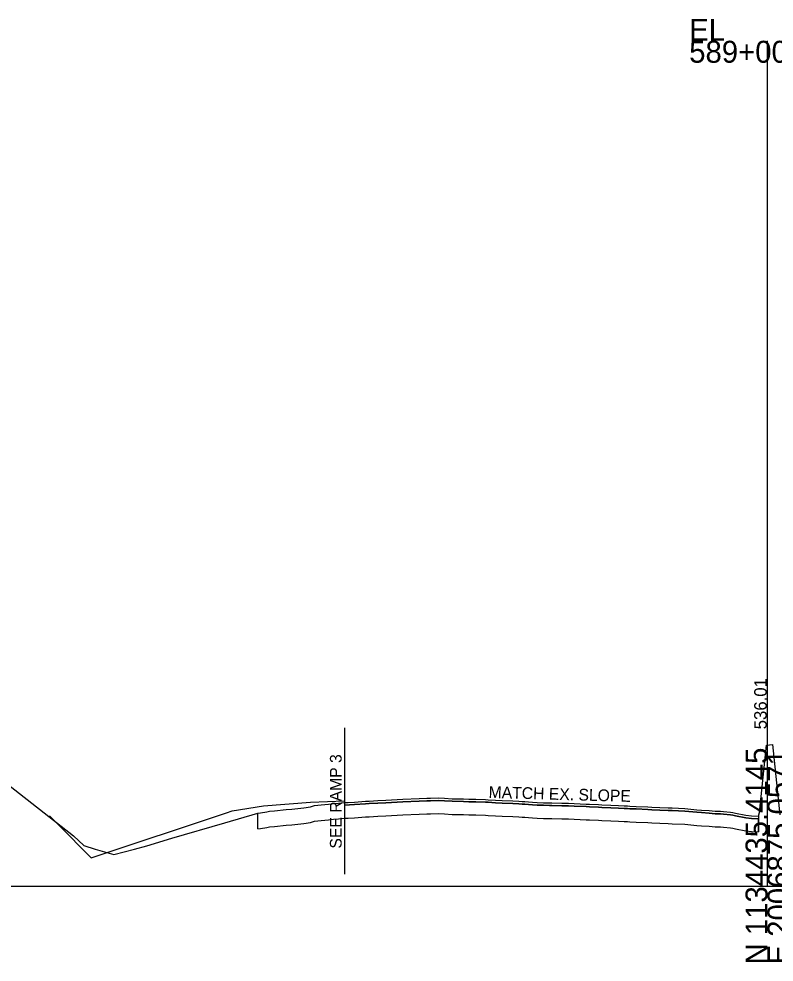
# Model space of a CAD drawing. Extents: x -201 to 2007062, y -213 to 1139737.
# Drawn here: x 1154.4 to 1250.8, y 3490.3 to 3610.7 of the extents above; entities that cross this region are included whole.
import ezdxf

# ---------------------------------------------------------------- set-up
doc = ezdxf.new("R2010")
doc.units = 0
for name, color, linetype in [('RD_DTM_Design_FG', 7, 'Continuous'), ('RD_GPK_XS_Cell', 7, 'Continuous'), ('RD_XS_ExGround', 7, 'Continuous'), ('RD_XS_ExPaveRet', 7, 'Continuous'), ('RD_XS_PaveOvlay', 7, 'Continuous'), ('RD_XS_SideStreet', 7, 'Continuous'), ('RD_XS_TX_Elev_EX', 7, 'Continuous'), ('RD_XS_TX_Slope', 7, 'Continuous')]:
    doc.layers.add(name, color=color, linetype=linetype)

msp = doc.modelspace()

# ---------------------------------------------------------------- linework, layer by layer
at = {"layer": 'RD_DTM_Design_FG'}
msp.add_lwpolyline([(1158.31, 3508.96), (1159.45, 3507.81), (1163.64, 3503.63), (1180.91, 3509.36), (1181.65, 3509.6), (1185.65, 3510.24), (1191.66, 3510.71), (1193.83, 3510.8), (1196, 3510.88)], dxfattribs=at)
at = {"layer": 'RD_GPK_XS_Cell'}
for p, q in [((1250, 3500), (1250, 3607.9)), ((1000, 3500), (1250, 3500)), ((1250, 3500), (1500, 3500))]:
    msp.add_line(p, q, dxfattribs=at)
at = {"layer": 'RD_XS_ExGround'}
msp.add_lwpolyline([(1149.11, 3516.02), (1161.36, 3506.42), (1162.68, 3505.18), (1164.16, 3504.73), (1166.52, 3504.03), (1169.17, 3504.71), (1170.74, 3505.15), (1173.95, 3506.11), (1180.69, 3508.07), (1184.9, 3509.31), (1185.24, 3509.36), (1186.08, 3509.51), (1186.42, 3509.56), (1187.04, 3509.62), (1188.54, 3509.78), (1189.25, 3509.85), (1190.79, 3510.02), (1191.64, 3510.13), (1192.15, 3510.3), (1193.02, 3510.4), (1193.95, 3510.49), (1194.59, 3510.55), (1195.21, 3510.6), (1195.65, 3510.65), (1197.27, 3510.74), (1198.66, 3510.84), (1199.15, 3510.87), (1200.22, 3510.94), (1201.27, 3510.99), (1203.45, 3511.1), (1205.51, 3511.19), (1206.49, 3511.24), (1206.98, 3511.24), (1208, 3511.26), (1208.77, 3511.22), (1209.75, 3511.17), (1211.19, 3511.13), (1211.87, 3511.11), (1212.76, 3511.09), (1214, 3511.06), (1214.33, 3511.04), (1215.26, 3510.99), (1216.12, 3510.94), (1217.46, 3510.88), (1218.24, 3510.84), (1218.69, 3510.81), (1219.03, 3510.79), (1219.49, 3510.76), (1219.99, 3510.73), (1220.59, 3510.7), (1221.4, 3510.66), (1222.16, 3510.63), (1222.48, 3510.62), (1223.73, 3510.6), (1224.6, 3510.58), (1225.3, 3510.55), (1226.86, 3510.48), (1227.26, 3510.46), (1228.43, 3510.41), (1228.85, 3510.39), (1230, 3510.33), (1230.97, 3510.29), (1231.71, 3510.25), (1232.11, 3510.24), (1232.42, 3510.23), (1233.25, 3510.19), (1234.7, 3510.12), (1235.21, 3510.09), (1236.27, 3510.05), (1237.33, 3510.01), (1237.83, 3509.98), (1239.45, 3509.9), (1240.97, 3509.76), (1241.57, 3509.72), (1242.53, 3509.65), (1243.33, 3509.59), (1243.98, 3509.57), (1244.39, 3509.54), (1245.26, 3509.44), (1245.59, 3509.4), (1245.91, 3509.3), (1247.24, 3509.07), (1247.94, 3509), (1248.86, 3508.93), (1248.99, 3509.4), (1249.87, 3518.01), (1250.63, 3518.08), (1251.59, 3509.09)], dxfattribs=at)
at = {"layer": 'RD_XS_ExPaveRet'}
for p, q in [((1196, 3510.33), (1196, 3508.67)), ((1184.9, 3507.31), (1184.9, 3509.31)), ((1191.64, 3508.13), (1192.15, 3508.3)), ((1192.15, 3508.3), (1193.02, 3508.4)), ((1193.02, 3508.4), (1193.95, 3508.49)), ((1193.95, 3508.49), (1194.59, 3508.55)), ((1194.59, 3508.55), (1195.21, 3508.6)), ((1195.21, 3508.6), (1195.65, 3508.65)), ((1195.65, 3508.65), (1197.27, 3508.74)), ((1196, 3508.67), (1197.27, 3508.74)), ((1197.27, 3508.74), (1198.66, 3508.84)), ((1197.27, 3508.74), (1198.66, 3508.84)), ((1198.66, 3508.84), (1199.15, 3508.87)), ((1198.66, 3508.84), (1199.15, 3508.87)), ((1199.15, 3508.87), (1200.22, 3508.94)), ((1199.15, 3508.87), (1200.22, 3508.94)), ((1200.22, 3508.94), (1201.27, 3508.99)), ((1200.22, 3508.94), (1201.27, 3508.99)), ((1201.27, 3508.99), (1203.45, 3509.1)), ((1201.27, 3508.99), (1203.45, 3509.1)), ((1203.45, 3509.1), (1205.51, 3509.19)), ((1203.45, 3509.1), (1205.51, 3509.19)), ((1205.51, 3509.19), (1206.49, 3509.24)), ((1205.51, 3509.19), (1206.49, 3509.24)), ((1206.49, 3509.24), (1206.98, 3509.24)), ((1206.49, 3509.24), (1206.98, 3509.24)), ((1206.98, 3509.24), (1208, 3509.26)), ((1206.98, 3509.24), (1208, 3509.26)), ((1208, 3509.26), (1208.77, 3509.22)), ((1208, 3509.26), (1208.77, 3509.22)), ((1208.77, 3509.22), (1209.75, 3509.17)), ((1208.77, 3509.22), (1209.75, 3509.17)), ((1209.75, 3509.17), (1211.19, 3509.13)), ((1209.75, 3509.17), (1211.19, 3509.13)), ((1211.19, 3509.13), (1211.87, 3509.11)), ((1211.19, 3509.13), (1211.87, 3509.11)), ((1211.87, 3509.11), (1212.76, 3509.09)), ((1211.87, 3509.11), (1212.76, 3509.09)), ((1212.76, 3509.09), (1214, 3509.06)), ((1212.76, 3509.09), (1214, 3509.06)), ((1214, 3509.06), (1214.33, 3509.04)), ((1214, 3509.06), (1214.33, 3509.04)), ((1214.33, 3509.04), (1215.26, 3508.99)), ((1214.33, 3509.04), (1215.26, 3508.99)), ((1215.26, 3508.99), (1216.12, 3508.94)), ((1215.26, 3508.99), (1216.12, 3508.94)), ((1216.12, 3508.94), (1217.46, 3508.88)), ((1216.12, 3508.94), (1217.46, 3508.88)), ((1217.46, 3508.88), (1218.24, 3508.84)), ((1217.46, 3508.88), (1218.24, 3508.84)), ((1218.24, 3508.84), (1218.69, 3508.81)), ((1218.24, 3508.84), (1218.69, 3508.81)), ((1218.69, 3508.81), (1219.03, 3508.79)), ((1218.69, 3508.81), (1219.03, 3508.79)), ((1219.03, 3508.79), (1219.49, 3508.76)), ((1219.03, 3508.79), (1219.49, 3508.76)), ((1219.49, 3508.76), (1219.99, 3508.73)), ((1219.49, 3508.76), (1219.99, 3508.73)), ((1219.99, 3508.73), (1220.59, 3508.7)), ((1219.99, 3508.73), (1220.59, 3508.7)), ((1220.59, 3508.7), (1221.4, 3508.66)), ((1220.59, 3508.7), (1221.4, 3508.66)), ((1221.4, 3508.66), (1222.16, 3508.63)), ((1221.4, 3508.66), (1222.16, 3508.63)), ((1222.16, 3508.63), (1222.48, 3508.62)), ((1222.16, 3508.63), (1222.48, 3508.62)), ((1222.48, 3508.62), (1223.73, 3508.6)), ((1222.48, 3508.62), (1223.73, 3508.6)), ((1223.73, 3508.6), (1224.6, 3508.58)), ((1223.73, 3508.6), (1224.6, 3508.58)), ((1224.6, 3508.58), (1225.3, 3508.55)), ((1224.6, 3508.58), (1225.3, 3508.55)), ((1225.3, 3508.55), (1226.86, 3508.48)), ((1225.3, 3508.55), (1226.86, 3508.48)), ((1226.86, 3508.48), (1227.26, 3508.46)), ((1226.86, 3508.48), (1227.26, 3508.46)), ((1227.26, 3508.46), (1228.43, 3508.41)), ((1227.26, 3508.46), (1228.43, 3508.41)), ((1228.43, 3508.41), (1228.85, 3508.39)), ((1228.43, 3508.41), (1228.85, 3508.39)), ((1228.85, 3508.39), (1230, 3508.33)), ((1228.85, 3508.39), (1230, 3508.33)), ((1230, 3508.33), (1230.97, 3508.29)), ((1230, 3508.33), (1230.97, 3508.29)), ((1230.97, 3508.29), (1231.71, 3508.25)), ((1230.97, 3508.29), (1231.71, 3508.25)), ((1231.71, 3508.25), (1232.11, 3508.24)), ((1231.71, 3508.25), (1232.11, 3508.24)), ((1232.11, 3508.24), (1232.42, 3508.23)), ((1232.11, 3508.24), (1232.42, 3508.23)), ((1232.42, 3508.23), (1233.25, 3508.19)), ((1232.42, 3508.23), (1233.25, 3508.19)), ((1248.86, 3508.93), (1248.86, 3506.93)), ((1248.86, 3506.93), (1248.86, 3508.6)), ((1184.9, 3507.31), (1185.24, 3507.36)), ((1185.24, 3507.36), (1186.08, 3507.51)), ((1186.08, 3507.51), (1186.42, 3507.56)), ((1186.42, 3507.56), (1187.04, 3507.62)), ((1187.04, 3507.62), (1188.54, 3507.78)), ((1188.54, 3507.78), (1189.25, 3507.85)), ((1189.25, 3507.85), (1190.79, 3508.02)), ((1190.79, 3508.02), (1191.64, 3508.13)), ((1233.25, 3508.19), (1234.7, 3508.12)), ((1233.25, 3508.19), (1234.7, 3508.12)), ((1234.7, 3508.12), (1235.21, 3508.09)), ((1234.7, 3508.12), (1235.21, 3508.09)), ((1235.21, 3508.09), (1236.27, 3508.05)), ((1235.21, 3508.09), (1236.27, 3508.05)), ((1236.27, 3508.05), (1237.33, 3508.01)), ((1236.27, 3508.05), (1237.33, 3508.01)), ((1237.33, 3508.01), (1237.83, 3507.98)), ((1237.33, 3508.01), (1237.83, 3507.98)), ((1237.83, 3507.98), (1239.45, 3507.9)), ((1237.83, 3507.98), (1239.45, 3507.9)), ((1239.45, 3507.9), (1240.97, 3507.76)), ((1239.45, 3507.9), (1240.97, 3507.76)), ((1240.97, 3507.76), (1241.57, 3507.72)), ((1240.97, 3507.76), (1241.57, 3507.72)), ((1241.57, 3507.72), (1242.53, 3507.65)), ((1241.57, 3507.72), (1242.53, 3507.65)), ((1242.53, 3507.65), (1243.33, 3507.59)), ((1242.53, 3507.65), (1243.33, 3507.59)), ((1243.33, 3507.59), (1243.98, 3507.57)), ((1243.33, 3507.59), (1243.98, 3507.57)), ((1243.98, 3507.57), (1244.39, 3507.54)), ((1243.98, 3507.57), (1244.39, 3507.54)), ((1244.39, 3507.54), (1245.26, 3507.44)), ((1244.39, 3507.54), (1245.26, 3507.44)), ((1245.26, 3507.44), (1245.59, 3507.4)), ((1245.26, 3507.44), (1245.59, 3507.4)), ((1245.59, 3507.4), (1245.91, 3507.3)), ((1245.59, 3507.4), (1245.91, 3507.3)), ((1245.91, 3507.3), (1247.24, 3507.07)), ((1245.91, 3507.3), (1247.24, 3507.07)), ((1247.24, 3507.07), (1247.94, 3507)), ((1247.24, 3507.07), (1247.94, 3507)), ((1247.94, 3507), (1248.86, 3506.93)), ((1247.94, 3507), (1248.86, 3506.93))]:
    msp.add_line(p, q, dxfattribs=at)
for points in [[(1248.86, 3508.6), (1247.94, 3508.66), (1247.24, 3508.73), (1245.91, 3508.97), (1245.59, 3509.07), (1245.26, 3509.11), (1244.39, 3509.2), (1243.98, 3509.23), (1243.33, 3509.25), (1242.53, 3509.32), (1241.57, 3509.39), (1240.97, 3509.43), (1239.45, 3509.56), (1237.83, 3509.65), (1237.33, 3509.68), (1236.27, 3509.72), (1235.21, 3509.75), (1234.7, 3509.79), (1233.25, 3509.86), (1232.42, 3509.89), (1232.11, 3509.91), (1231.71, 3509.92), (1230.97, 3509.96), (1230, 3510), (1228.85, 3510.06), (1228.43, 3510.08), (1227.26, 3510.13), (1226.86, 3510.15), (1225.3, 3510.22), (1224.6, 3510.24), (1223.73, 3510.26), (1222.48, 3510.29), (1222.16, 3510.3), (1221.4, 3510.33), (1220.59, 3510.36), (1219.99, 3510.39), (1219.49, 3510.42), (1219.03, 3510.45), (1218.69, 3510.48), (1218.24, 3510.51), (1217.46, 3510.55), (1216.12, 3510.61), (1215.26, 3510.66), (1214.33, 3510.71), (1214, 3510.72), (1212.76, 3510.75), (1211.87, 3510.77), (1211.19, 3510.79), (1209.75, 3510.84), (1208.77, 3510.89), (1208, 3510.93), (1206.98, 3510.91), (1206.49, 3510.9), (1205.51, 3510.86), (1203.45, 3510.77), (1201.27, 3510.66), (1200.22, 3510.61), (1199.15, 3510.54), (1198.66, 3510.51), (1197.27, 3510.41), (1196, 3510.33)], [(1248.86, 3508.6), (1248.86, 3508.6)]]:
    msp.add_lwpolyline(points, dxfattribs=at)
at = {"layer": 'RD_XS_PaveOvlay'}
msp.add_line((1196, 3510.67), (1196, 3510.33), dxfattribs=at)
for points in [[(1196, 3510.67), (1197.27, 3510.74), (1198.66, 3510.84), (1199.15, 3510.87), (1200.22, 3510.94), (1201.27, 3510.99), (1203.45, 3511.1), (1205.51, 3511.19), (1206.49, 3511.24), (1206.98, 3511.24), (1208, 3511.26), (1208.77, 3511.22), (1209.75, 3511.17), (1211.19, 3511.13), (1211.87, 3511.11), (1212.76, 3511.09), (1214, 3511.06), (1214.33, 3511.04), (1215.26, 3510.99), (1216.12, 3510.94), (1217.46, 3510.88), (1218.24, 3510.84), (1218.69, 3510.81), (1219.03, 3510.79), (1219.49, 3510.76), (1219.99, 3510.73), (1220.59, 3510.7), (1221.4, 3510.66), (1222.16, 3510.63), (1222.48, 3510.62), (1223.73, 3510.6), (1224.6, 3510.58), (1225.3, 3510.55), (1226.86, 3510.48), (1227.26, 3510.46), (1228.43, 3510.41), (1228.85, 3510.39), (1230, 3510.33), (1230.97, 3510.29), (1231.71, 3510.25), (1232.11, 3510.24), (1232.42, 3510.23), (1233.25, 3510.19), (1234.7, 3510.12), (1235.21, 3510.09), (1236.27, 3510.05), (1237.33, 3510.01), (1237.83, 3509.98), (1239.45, 3509.9), (1240.97, 3509.76), (1241.57, 3509.72), (1242.53, 3509.65), (1243.33, 3509.59), (1243.98, 3509.57), (1244.39, 3509.54), (1245.26, 3509.44), (1245.59, 3509.4), (1245.91, 3509.3), (1247.24, 3509.07), (1247.94, 3509), (1248.86, 3508.93)], [(1196, 3510.33), (1197.27, 3510.41), (1198.66, 3510.51), (1199.15, 3510.54), (1200.22, 3510.61), (1201.27, 3510.66), (1203.45, 3510.77), (1205.51, 3510.86), (1206.49, 3510.9), (1206.98, 3510.91), (1208, 3510.93), (1208.77, 3510.89), (1209.75, 3510.84), (1211.19, 3510.79), (1211.87, 3510.77), (1212.76, 3510.75), (1214, 3510.72), (1214.33, 3510.71), (1215.26, 3510.66), (1216.12, 3510.61), (1217.46, 3510.55), (1218.24, 3510.51), (1218.69, 3510.48), (1219.03, 3510.45), (1219.49, 3510.42), (1219.99, 3510.39), (1220.59, 3510.36), (1221.4, 3510.33), (1222.16, 3510.3), (1222.48, 3510.29), (1223.73, 3510.26), (1224.6, 3510.24), (1225.3, 3510.22), (1226.86, 3510.15), (1227.26, 3510.13), (1228.43, 3510.08), (1228.85, 3510.06), (1230, 3510), (1230.97, 3509.96), (1231.71, 3509.92), (1232.11, 3509.91), (1232.42, 3509.89), (1233.25, 3509.86), (1234.7, 3509.79), (1235.21, 3509.75), (1236.27, 3509.72), (1237.33, 3509.68), (1237.83, 3509.65), (1239.45, 3509.56), (1240.97, 3509.43), (1241.57, 3509.39), (1242.53, 3509.32), (1243.33, 3509.25), (1243.98, 3509.23), (1244.39, 3509.2), (1245.26, 3509.11), (1245.59, 3509.07), (1245.91, 3508.97), (1247.24, 3508.73), (1247.94, 3508.66), (1248.86, 3508.6)]]:
    msp.add_lwpolyline(points, dxfattribs=at)
at = {"layer": 'RD_XS_SideStreet'}
msp.add_line((1196, 3520.21), (1196, 3501.53), dxfattribs=at)

# ---------------------------------------------------------------- texts
at = {"layer": 'RD_GPK_XS_Cell'}
for s, p in [('EL', (1240, 3607.9)), ('589+00.00 / 1', (1240, 3605.1))]:
    msp.add_text(s, height=2.8, dxfattribs=at).set_placement(p)
for s, p in [('N 1134435.4145', (1250, 3490)), ('E 2006875.0571', (1252.8, 3490))]:
    msp.add_text(s, height=2.8, rotation=90, dxfattribs=at).set_placement(p)
at = {"layer": 'RD_XS_SideStreet'}
msp.add_text('SEE RAMP 3', height=1.5, rotation=90, dxfattribs=at).set_placement((1195.62, 3504.8))
at = {"layer": 'RD_XS_TX_Elev_EX'}
msp.add_text('536.01', height=1.6, rotation=90, dxfattribs=at).set_placement((1249.9, 3520.02))
at = {"layer": 'RD_XS_TX_Slope'}
msp.add_text('MATCH EX. SLOPE', height=1.5, rotation=358.3671, dxfattribs=at).set_placement((1214.37, 3511.27))

doc.saveas('drawing.dxf')
